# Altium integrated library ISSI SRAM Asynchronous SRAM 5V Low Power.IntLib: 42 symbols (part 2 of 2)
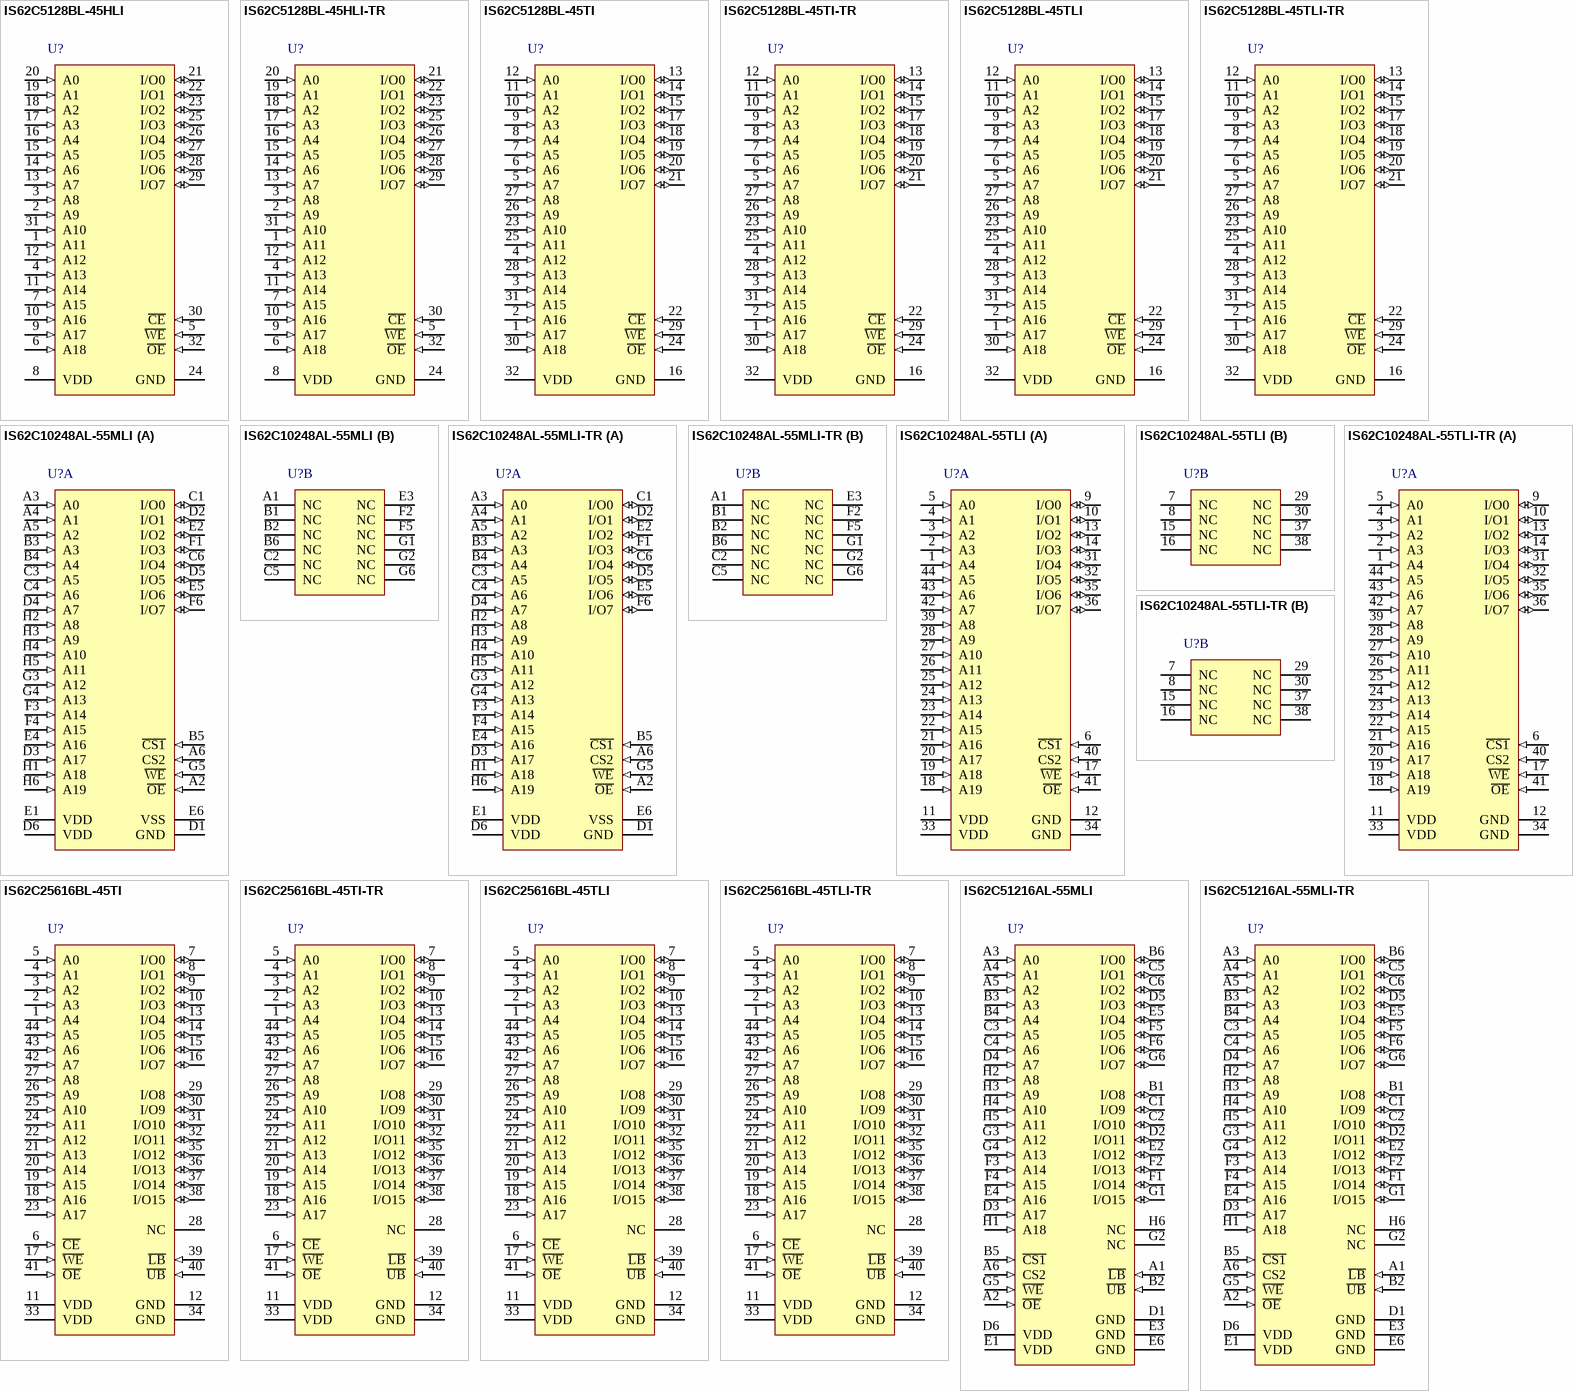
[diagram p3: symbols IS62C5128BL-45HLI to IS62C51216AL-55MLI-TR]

## IS62C25616BL-45TLI-TR
designator U?
4 M High Speed CMOS SRAM, 256 K x 16, -40 to 85 degC, 44-Pin SOP (TSOP-2-44), Pb-Free; Manufacturer: Integrated Silicon Solution Inc (ISSI); PartNumber: IS62C25616BL-45TLI-TR; Density: 4M; Packing: Tape & Reel; Speed (ns): 45
footprint ISSI-TSOP-2-44_N (SOP, 44-Leads, Body 18.5x10.3mm, Pitch 0.8mm, IPC Medium Density)
pins: 1 A4 (in) "Address Input", 2 A3 (in) "Address Input", 3 A2 (in) "Address Input", 4 A1 (in) "Address Input", 5 A0 (in) "Address Input", 6 ~{CE} (in) "Chip Enable Input", 7 I/O0 (io) "Data Input/Output", 8 I/O1 (io) "Data Input/Output", 9 I/O2 (io) "Data Input/Output", 10 I/O3 (io) "Data Input/Output", 11 VDD (power) "Power", 12 GND (power) "Ground", 13 I/O4 (io) "Data Input/Output", 14 I/O5 (io) "Data Input/Output", 15 I/O6 (io) "Data Input/Output", 16 I/O7 (io) "Data Input/Output", 17 ~{WE} (in) "Write Enable Input", 18 A16 (in) "Address Input", 19 A15 (in) "Address Input", 20 A14 (in) "Address Input", 21 A13 (in) "Address Input", 22 A12 (in) "Address Input", 23 A17 (in) "Address Input", 24 A11 (in) "Address Input", 25 A10 (in) "Address Input", 26 A9 (in) "Address Input", 27 A8 (in) "Address Input", 28 NC "No Connection", 29 I/O8 (io) "Data Input/Output", 30 I/O9 (io) "Data Input/Output", 31 I/O10 (io) "Data Input/Output", 32 I/O11 (io) "Data Input/Output", 33 VDD (power) "Power", 34 GND (power) "Ground", 35 I/O12 (io) "Data Input/Output", 36 I/O13 (io) "Data Input/Output", 37 I/O14 (io) "Data Inputs/Outputs", 38 I/O15 (io) "Data Input/Output", 39 ~{LB} (in) "Lower-byte Control (I/O0-I/O7)", 40 ~{UB} (in) "Upper-byte Control (I/O8-I/O15)", 41 ~{OE} (in) "Output Enable Input", 42 A7 (in) "Address Input", 43 A6 (in) "Address Input", 44 A5 (in) "Address Input"

## IS62C51216AL-55MLI
designator U?
8 M Low Voltage, Ultra Low Power CMOS SRAM, 512 K x 16, -40 to 85 degC, 48-Pin BGA (TF-BGA-48), Pb-Free; Manufacturer: Integrated Silicon Solution Inc (ISSI); PartNumber: IS62C51216AL-55MLI; Density: 8M; Packing: Tray / Tube; Speed (ns): 55
footprint ISSI-TF-BGA-48-9000x11000DE (BGA, 48-Balls, Body 11x9mm, Pitch 0.75mm)
pins: A1 ~{LB} (in) "Lower-byte Control (I/O0-I/O7)", A2 ~{OE} (in) "Output Enable Input", A3 A0 (in) "Address Input", A4 A1 (in) "Address Input", A5 A2 (in) "Address Input", A6 CS2 (in) "Chip Enable Input", B1 I/O8 (io) "Data Input/Output", B2 ~{UB} (in) "Upper-byte Control (I/O8-I/O15)", B3 A3 (in) "Address Input", B4 A4 (in) "Address Input", B5 ~{CS1} (in) "Chip Enable Input", B6 I/O0 (io) "Data Input/Output", C1 I/O9 (io) "Data Input/Output", C2 I/O10 (io) "Data Input/Output", C3 A5 (in) "Address Input", C4 A6 (in) "Address Input", C5 I/O1 (io) "Data Input/Output", C6 I/O2 (io) "Data Input/Output", D1 GND (power) "Ground", D2 I/O11 (io) "Data Input/Output", D3 A17 (in) "Address Input", D4 A7 (in) "Address Input", D5 I/O3 (io) "Data Input/Output", D6 VDD (power) "Power", E1 VDD (power) "Power", E2 I/O12 (io) "Data Input/Output", E3 GND (power) "Ground", E4 A16 (in) "Address Input", E5 I/O4 (io) "Data Input/Output", E6 GND (power) "Ground", F1 I/O14 (io) "Data Input/Output", F2 I/O13 (io) "Data Input/Output", F3 A14 (in) "Address Input", F4 A15 (in) "Address Input", F5 I/O5 (io) "Data Input/Output", F6 I/O6 (io) "Data Input/Output", G1 I/O15 (io) "Data Input/Output", G2 NC "No Connection", G3 A12 (in) "Address Input", G4 A13 (in) "Address Input", G5 ~{WE} (in) "Write Enable Input", G6 I/O7 (io) "Data Input/Output", H1 A18 (in) "Address Input", H2 A8 (in) "Address Input", H3 A9 (in) "Address Input", H4 A10 (in) "Address Input", H5 A11 (in) "Address Input", H6 NC "No Connection"

## IS62C51216AL-55MLI-TR
designator U?
8 M Low Voltage, Ultra Low Power CMOS SRAM, 512 K x 16, -40 to 85 degC, 48-Pin BGA (TF-BGA-48), Pb-Free; Manufacturer: Integrated Silicon Solution Inc (ISSI); PartNumber: IS62C51216AL-55MLI-TR; Density: 8M; Packing: Tape & Reel; Speed (ns): 55
footprint ISSI-TF-BGA-48-9000x11000DE (BGA, 48-Balls, Body 11x9mm, Pitch 0.75mm)
pins: A1 ~{LB} (in) "Lower-byte Control (I/O0-I/O7)", A2 ~{OE} (in) "Output Enable Input", A3 A0 (in) "Address Input", A4 A1 (in) "Address Input", A5 A2 (in) "Address Input", A6 CS2 (in) "Chip Enable Input", B1 I/O8 (io) "Data Input/Output", B2 ~{UB} (in) "Upper-byte Control (I/O8-I/O15)", B3 A3 (in) "Address Input", B4 A4 (in) "Address Input", B5 ~{CS1} (in) "Chip Enable Input", B6 I/O0 (io) "Data Input/Output", C1 I/O9 (io) "Data Input/Output", C2 I/O10 (io) "Data Input/Output", C3 A5 (in) "Address Input", C4 A6 (in) "Address Input", C5 I/O1 (io) "Data Input/Output", C6 I/O2 (io) "Data Input/Output", D1 GND (power) "Ground", D2 I/O11 (io) "Data Input/Output", D3 A17 (in) "Address Input", D4 A7 (in) "Address Input", D5 I/O3 (io) "Data Input/Output", D6 VDD (power) "Power", E1 VDD (power) "Power", E2 I/O12 (io) "Data Input/Output", E3 GND (power) "Ground", E4 A16 (in) "Address Input", E5 I/O4 (io) "Data Input/Output", E6 GND (power) "Ground", F1 I/O14 (io) "Data Input/Output", F2 I/O13 (io) "Data Input/Output", F3 A14 (in) "Address Input", F4 A15 (in) "Address Input", F5 I/O5 (io) "Data Input/Output", F6 I/O6 (io) "Data Input/Output", G1 I/O15 (io) "Data Input/Output", G2 NC "No Connection", G3 A12 (in) "Address Input", G4 A13 (in) "Address Input", G5 ~{WE} (in) "Write Enable Input", G6 I/O7 (io) "Data Input/Output", H1 A18 (in) "Address Input", H2 A8 (in) "Address Input", H3 A9 (in) "Address Input", H4 A10 (in) "Address Input", H5 A11 (in) "Address Input", H6 NC "No Connection"

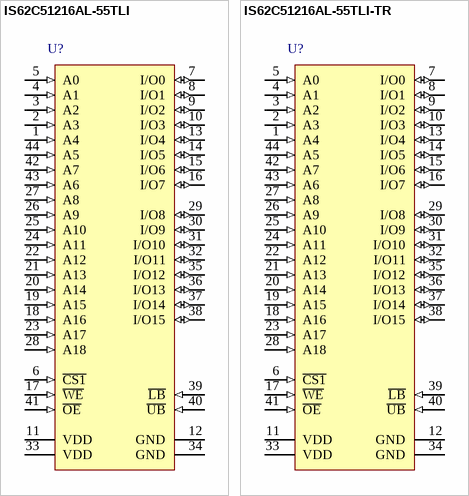
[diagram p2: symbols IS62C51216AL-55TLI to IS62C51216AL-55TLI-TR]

## IS62C51216AL-55TLI
designator U?
8 M Low Voltage, Ultra Low Power CMOS SRAM, 512 K x 16, -40 to 85 degC, 44-Pin SOP (TSOP-2-44), Pb-Free; Manufacturer: Integrated Silicon Solution Inc (ISSI); PartNumber: IS62C51216AL-55TLI; Density: 8M; Packing: Tray / Tube; Speed (ns): 55
footprint ISSI-TSOP-2-44_N (SOP, 44-Leads, Body 18.5x10.3mm, Pitch 0.8mm, IPC Medium Density)
pins: 1 A4 (in) "Address Input", 2 A3 (in) "Address Input", 3 A2 (in) "Address Input", 4 A1 (in) "Address Input", 5 A0 (in) "Address Input", 6 ~{CS1} (in) "Chip Enable Input", 7 I/O0 (io) "Data Input/Output", 8 I/O1 (io) "Data Input/Output", 9 I/O2 (io) "Data Input/Output", 10 I/O3 (io) "Data Input/Output", 11 VDD (power) "Power", 12 GND (power) "Ground", 13 I/O4 (io) "Data Input/Output", 14 I/O5 (io) "Data Input/Output", 15 I/O6 (io) "Data Input/Output", 16 I/O7 (io) "Data Input/Output", 17 ~{WE} (in) "Write Enable Input", 18 A16 (in) "Address Input", 19 A15 (in) "Address Input", 20 A14 (in) "Address Input", 21 A13 (in) "Address Input", 22 A12 (in) "Address Input", 23 A17 (in) "Address Input", 24 A11 (in) "Address Input", 25 A10 (in) "Address Input", 26 A9 (in) "Address Input", 27 A8 (in) "Address Input", 28 A18 (in) "Address Input", 29 I/O8 (io) "Data Input/Output", 30 I/O9 (io) "Data Input/Output", 31 I/O10 (io) "Data Input/Output", 32 I/O11 (io) "Data Input/Output", 33 VDD (power) "Power", 34 GND (power) "Ground", 35 I/O12 (io) "Data Input/Output", 36 I/O13 (io) "Data Input/Output", 37 I/O14 (io) "Data Input/Output", 38 I/O15 (io) "Data Input/Output", 39 ~{LB} (in) "Lower-byte Control (I/O0-I/O7)", 40 ~{UB} (in) "Upper-byte Control (I/O8-I/O15)", 41 ~{OE} (in) "Output Enable Input", 42 A7 (in) "Address Input", 43 A6 (in) "Address Input", 44 A5 (in) "Address Input"

## IS62C51216AL-55TLI-TR
designator U?
8 M Low Voltage, Ultra Low Power CMOS SRAM, 512 K x 16, -40 to 85 degC, 44-Pin SOP (TSOP-2-44), Pb-Free; Manufacturer: Integrated Silicon Solution Inc (ISSI); PartNumber: IS62C51216AL-55TLI-TR; Density: 8M; Packing: Tape & Reel; Speed (ns): 55
footprint ISSI-TSOP-2-44_N (SOP, 44-Leads, Body 18.5x10.3mm, Pitch 0.8mm, IPC Medium Density)
pins: 1 A4 (in) "Address Input", 2 A3 (in) "Address Input", 3 A2 (in) "Address Input", 4 A1 (in) "Address Input", 5 A0 (in) "Address Input", 6 ~{CS1} (in) "Chip Enable Input", 7 I/O0 (io) "Data Input/Output", 8 I/O1 (io) "Data Input/Output", 9 I/O2 (io) "Data Input/Output", 10 I/O3 (io) "Data Input/Output", 11 VDD (power) "Power", 12 GND (power) "Ground", 13 I/O4 (io) "Data Input/Output", 14 I/O5 (io) "Data Input/Output", 15 I/O6 (io) "Data Input/Output", 16 I/O7 (io) "Data Input/Output", 17 ~{WE} (in) "Write Enable Input", 18 A16 (in) "Address Input", 19 A15 (in) "Address Input", 20 A14 (in) "Address Input", 21 A13 (in) "Address Input", 22 A12 (in) "Address Input", 23 A17 (in) "Address Input", 24 A11 (in) "Address Input", 25 A10 (in) "Address Input", 26 A9 (in) "Address Input", 27 A8 (in) "Address Input", 28 A18 (in) "Address Input", 29 I/O8 (io) "Data Input/Output", 30 I/O9 (io) "Data Input/Output", 31 I/O10 (io) "Data Input/Output", 32 I/O11 (io) "Data Input/Output", 33 VDD (power) "Power", 34 GND (power) "Ground", 35 I/O12 (io) "Data Input/Output", 36 I/O13 (io) "Data Input/Output", 37 I/O14 (io) "Data Input/Output", 38 I/O15 (io) "Data Input/Output", 39 ~{LB} (in) "Lower-byte Control (I/O0-I/O7)", 40 ~{UB} (in) "Upper-byte Control (I/O8-I/O15)", 41 ~{OE} (in) "Output Enable Input", 42 A7 (in) "Address Input", 43 A6 (in) "Address Input", 44 A5 (in) "Address Input"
